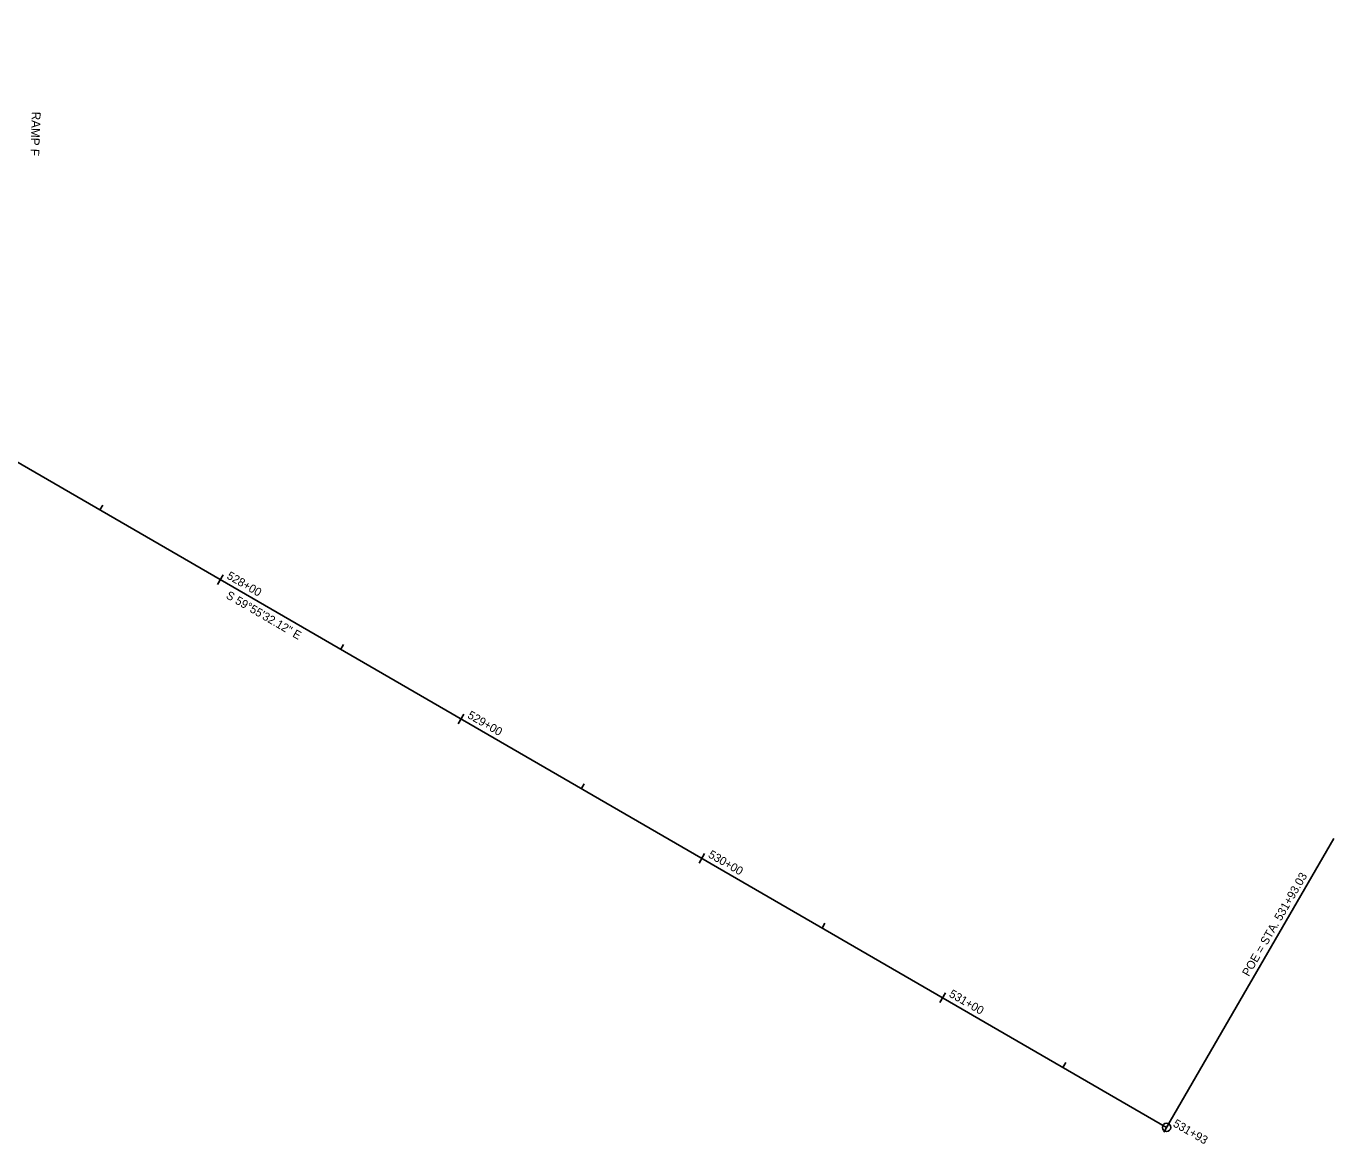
# Model space of a CAD drawing. Extents: x 1743277 to 1746745, y 462828 to 464839.
# Drawn here: x 1746275 to 1746745, y 462827.5 to 463229.4 of the extents above; entities that cross this region are included whole.
import ezdxf

# ---------------------------------------------------------------- set-up
doc = ezdxf.new("R2010")
doc.units = 0
for name, color, linetype in [('ANNOTATION', 7, 'Continuous'), ('D_Roadway_Centerline', 7, 'Continuous'), ('D_Roadway_Centerline_Bearings', 7, 'Continuous'), ('D_Roadway_Centerline_Flags', 7, 'Continuous'), ('D_Roadway_Centerline_Text', 7, 'Continuous')]:
    doc.layers.add(name, color=color, linetype=linetype)

msp = doc.modelspace()

# ---------------------------------------------------------------- linework, layer by layer
at = {"layer": 'D_Roadway_Centerline'}
msp.add_line((1746001.1, 463229.43), (1746684.88, 462833.47), dxfattribs=at)
at = {"layer": 'D_Roadway_Centerline_Flags'}
msp.add_lwpolyline([(1746684.88, 462833.47), (1746745.01, 462937.31)], dxfattribs=at)
msp.add_circle((1746684.88, 462833.47), 1.5, dxfattribs=at)
at = {"layer": 'D_Roadway_Centerline_Text'}
for points in [[(1746302.49, 463057.22), (1746301.49, 463055.48)], [(1746345.76, 463032.16), (1746343.75, 463028.7)], [(1746389.03, 463007.1), (1746388.02, 463005.37)], [(1746432.29, 462982.05), (1746430.29, 462978.58)], [(1746475.56, 462956.99), (1746474.56, 462955.26)], [(1746518.83, 462931.93), (1746516.83, 462928.47)], [(1746562.1, 462906.88), (1746561.1, 462905.15)], [(1746605.37, 462881.82), (1746603.37, 462878.36)], [(1746648.64, 462856.77), (1746647.64, 462855.03)], [(1746685.88, 462835.2), (1746683.87, 462831.74)]]:
    msp.add_lwpolyline(points, dxfattribs=at)

# ---------------------------------------------------------------- texts
at = {"layer": 'ANNOTATION'}
msp.add_text('RAMP F', height=3.15, rotation=267.9846, dxfattribs=at).set_placement((1746277.03, 463198.71))
at = {"layer": 'D_Roadway_Centerline_Bearings'}
msp.add_text('S 59%%d55\'32.12" E', height=3, rotation=329.9256, dxfattribs=at).set_placement((1746346.53, 463023.93))
at = {"layer": 'D_Roadway_Centerline_Flags'}
msp.add_text('POE = STA. 531+93.03', height=3, rotation=59.9256, dxfattribs=at).set_placement((1746714.44, 462887.51))
at = {"layer": 'D_Roadway_Centerline_Text'}
for s, p in [('528+00', (1746346.8, 463030.97)), ('529+00', (1746433.34, 462980.86)), ('530+00', (1746519.88, 462930.75)), ('531+00', (1746606.42, 462880.64)), ('531+93', (1746686.93, 462834.02))]:
    msp.add_text(s, height=3, rotation=329.9256, dxfattribs=at).set_placement(p)

doc.saveas('drawing.dxf')
